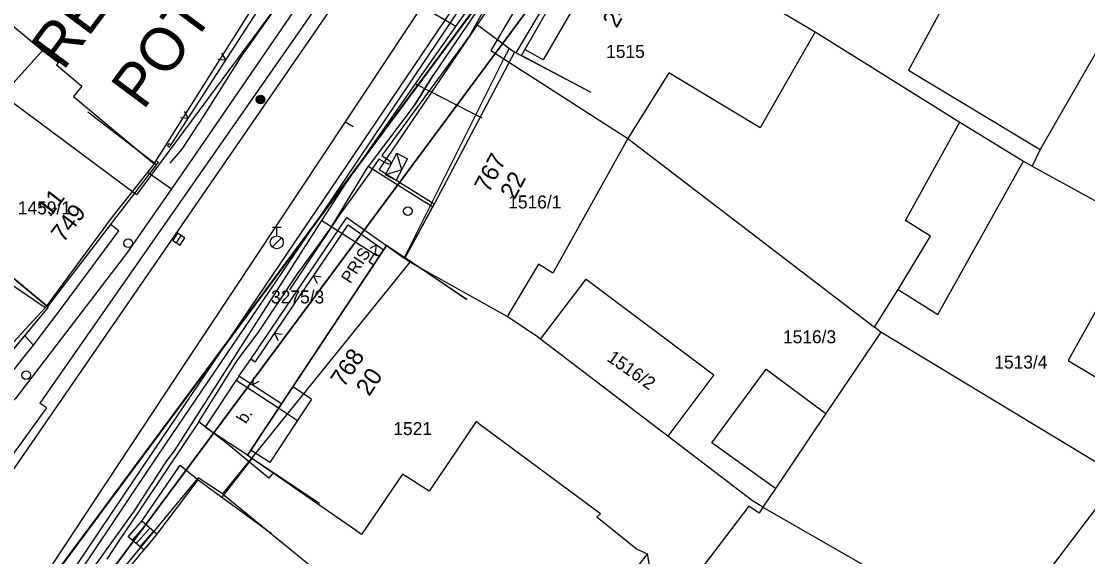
# Model space of a CAD drawing. Extents: x -601580 to 4, y -1204314 to 4.
# Drawn here: x -600312 to -600250.5, y -1203870.6 to -1203839.7 of the extents above; entities that cross this region are included whole.
import ezdxf

# ---------------------------------------------------------------- set-up
doc = ezdxf.new("R2010")
doc.units = 0
for name, color, linetype in [('00-EON NN', 7, 'Continuous'), ('00-INNOGY-NTL', 7, 'Continuous'), ('00-KN-HRANICE PARCEL', 7, 'Continuous'), ('00-KN-PARC. CISLA', 7, 'Continuous'), ('00-KN-VNITRNI KRESBA', 7, 'Continuous'), ('00-POLOHOPIS', 7, 'Continuous'), ('00-RAZÍTKO', 7, 'Continuous'), ('00-SITE KOM. KABEL', 7, 'Continuous'), ('00-VAK-VODA-RAD IGIS', 7, 'Continuous'), ('11-REKONSTRUKCE VODOVOD POPIS', 7, 'Continuous'), ('Vrstva 25', 7, 'Continuous'), ('Vrstva 27', 7, 'Continuous'), ('Vrstva 28', 7, 'Continuous'), ('Vrstva 9', 7, 'Continuous')]:
    doc.layers.add(name, color=color, linetype=linetype)

# ---------------------------------------------------------------- blocks, each defined once
blk = doc.blocks.new('6.14A_88')
at = {"layer": 'Vrstva 28'}
blk.add_circle((0, 0), 0.25, dxfattribs=at)
blk = doc.blocks.new('6.14A_90')
at = {"layer": 'Vrstva 28'}
blk.add_circle((0, 0), 0.25, dxfattribs=at)
blk = doc.blocks.new('6.30_44')
at = {"layer": 'Vrstva 27'}
blk.add_line((-0.25, 0), (0.25, 0), dxfattribs=at)
blk.add_lwpolyline([(-0.25, -0.25), (0.25, -0.25), (0.25, 0.25), (-0.25, 0.25)], close=True, dxfattribs=at)
blk = doc.blocks.new('6.14A_94')
at = {"layer": 'Vrstva 28'}
blk.add_circle((0, 0), 0.25, dxfattribs=at)
blk = doc.blocks.new('6.01A_1052')
at = {"layer": 'Vrstva 25'}
for radius in [0.25, 0.2, 0.15, 0.1, 0.05]:
    blk.add_circle((0, 0), radius, dxfattribs=at)
blk = doc.blocks.new('6.13_78')
at = {"layer": 'Vrstva 28'}
for p, q in [((-0.25, 0.875), (0.25, 0.875)), ((0, 0.375), (0, 0.875)), ((-0.258, -0.272), (0.272, 0.258))]:
    blk.add_line(p, q, dxfattribs=at)
blk.add_circle((0, 0), 0.375, dxfattribs=at)
blk = doc.blocks.new('NN630')
at = {"layer": 'Vrstva 9'}
for points in [[(-3, -700), (-703, 0)], [(-703, -700), (-703, 0), (697, 0), (697, -700)], [(-3, -700), (697, 0)], [(-703, -700), (697, -700)]]:
    blk.add_lwpolyline(points, dxfattribs=at)

msp = doc.modelspace()

# ---------------------------------------------------------------- linework, layer by layer
for points in [[(-600312.703, -1203875.115), (-600310.695, -1203876.605), (-600248.083, -1203792.252), (-600250.091, -1203790.762)], [(-600312.703, -1203875.115), (-600310.695, -1203876.605), (-600248.083, -1203792.252), (-600250.091, -1203790.762)], [(-600312.703, -1203875.115), (-600310.695, -1203876.605), (-600248.083, -1203792.252), (-600250.091, -1203790.762)], [(-600311.213, -1203873.107), (-600251.581, -1203792.77)], [(-600311.213, -1203873.107), (-600251.581, -1203792.77)], [(-600311.213, -1203873.107), (-600251.581, -1203792.77)]]:
    msp.add_lwpolyline(points)
at = {"layer": '00-EON NN'}
for points in [[(-600302.211, -1203810.212), (-600301.35, -1203810.158), (-600300.26, -1203809.69), (-600299, -1203809.18), (-600295.68, -1203811.31), (-600295.91, -1203813.74), (-600299.22, -1203819.65), (-600299.94, -1203821.57), (-600298.78, -1203824.75), (-600294.83, -1203832.08), (-600294.26, -1203833.07), (-600296.42, -1203837.59), (-600299.4, -1203841.82), (-600301.5, -1203845.15), (-600302.77, -1203847.1), (-600303.467, -1203847.911)], [(-600283.734, -1203836.176), (-600286.17, -1203840.55), (-600291.238, -1203847.458), (-600290.75, -1203847.79), (-600290.685, -1203847.95), (-600290.867, -1203847.962), (-600291.397, -1203847.665), (-600291.746, -1203848.17), (-600291.884, -1203848.405), (-600293.721, -1203850.951), (-600296.565, -1203855.206)]]:
    msp.add_lwpolyline(points, dxfattribs=at)
at = {"layer": '00-INNOGY-NTL'}
for p, q in [((-600289.28, -1203843.32), (-600285.46, -1203845.29)), ((-600304.77, -1203848.41), (-600303.37, -1203849.38)), ((-600294.69, -1203851.21), (-600291.52, -1203853.24))]:
    msp.add_line(p, q, dxfattribs=at)
for points in [[(-600286.96, -1203840.01), (-600294.08, -1203835.84), (-600301.99, -1203847.39), (-600303.37, -1203849.38), (-600305.92, -1203853.05), (-600312.38, -1203861.49), (-600319.31, -1203868.9), (-600323.47, -1203873.13), (-600326.97, -1203877.3), (-600332.51, -1203884.94)], [(-600309.72, -1203873.84), (-600305.47, -1203867.91), (-600303.72, -1203865.19), (-600303.17, -1203864.44), (-600294.69, -1203851.21), (-600293.31, -1203849.07), (-600289.28, -1203843.32), (-600286.96, -1203840.01), (-600284.34, -1203836.29)]]:
    msp.add_lwpolyline(points, dxfattribs=at)
at = {"layer": '00-KN-HRANICE PARCEL'}
for p, q in [((-600304.37, -1203847.94), (-600297.5, -1203837.03)), ((-600289.93, -1203853.38), (-600284.19, -1203841.89)), ((-600254.18, -1203847.79), (-600253.67, -1203848.08)), ((-600253.67, -1203848.08), (-600247.28, -1203851.58)), ((-600310.66, -1203856.26), (-600315.41, -1203853.03)), ((-600289.62, -1203853.62), (-600298.75, -1203864.93)), ((-600289.62, -1203853.62), (-600289.93, -1203853.38)), ((-600317.9, -1203864.02), (-600310.66, -1203856.26)), ((-600262.42, -1203857.65), (-600265.58, -1203862.35)), ((-600262.42, -1203857.65), (-600262.77, -1203857.36)), ((-600248.61, -1203866.01), (-600262.42, -1203857.65)), ((-600265.58, -1203862.35), (-600268.5, -1203866.68)), ((-600298.75, -1203864.93), (-600300.43, -1203866.99)), ((-600255.78, -1203875.46), (-600248.61, -1203866.01)), ((-600268.5, -1203866.68), (-600269.22, -1203867.76)), ((-600269.22, -1203867.76), (-600255.78, -1203875.46))]:
    msp.add_line(p, q, dxfattribs=at)
for points in [[(-600320.57, -1203832.25), (-600319.28, -1203833.49), (-600317.47, -1203835.44), (-600314.63, -1203838.22), (-600310.82, -1203841.4), (-600309.9, -1203842.1), (-600310.01, -1203842.23), (-600308.56, -1203843.46), (-600309.03, -1203844.05), (-600304.37, -1203847.94)], [(-600279.86, -1203832.78), (-600284.94, -1203841.4), (-600284.19, -1203841.89)], [(-600279.86, -1203832.78), (-600278.6, -1203833.34), (-600272.16, -1203836.8), (-600266.21, -1203840.33), (-600257.86, -1203845.53), (-600254.18, -1203847.79)], [(-600247.97, -1203837.99), (-600253.21, -1203847.11), (-600253.67, -1203848.08)], [(-600284.19, -1203841.89), (-600277.02, -1203846.48), (-600262.77, -1203857.36)], [(-600262.77, -1203857.36), (-600261.42, -1203855.19), (-600259.13, -1203856.63), (-600254.18, -1203847.79)], [(-600304.37, -1203847.94), (-600306.85, -1203851.07), (-600310.66, -1203856.26)], [(-600247.28, -1203851.58), (-600251.59, -1203859.29), (-600240.31, -1203866.07), (-600242.22, -1203869.32)], [(-600298.75, -1203864.93), (-600298.99, -1203864.76), (-600290.96, -1203852.65), (-600289.93, -1203853.38)], [(-600282.06, -1203858.06), (-600282.24, -1203857.93), (-600284, -1203856.75), (-600289.62, -1203853.62)], [(-600282.06, -1203858.06), (-600279.43, -1203854.6), (-600272.05, -1203860.13), (-600274.71, -1203863.67)], [(-600274.71, -1203863.67), (-600274.95, -1203863.49), (-600282.06, -1203858.06)], [(-600268.5, -1203866.68), (-600272.17, -1203864.05), (-600269.03, -1203859.79), (-600265.58, -1203862.35)], [(-600269.22, -1203867.76), (-600269.82, -1203867.4), (-600274.71, -1203863.67)], [(-600300.43, -1203866.99), (-600301.84, -1203866.07), (-600311.72, -1203878)], [(-600300.43, -1203866.99), (-600295.17, -1203871.27), (-600289.27, -1203875.09), (-600285.06, -1203877.94)], [(-600269.22, -1203867.76), (-600269.44, -1203868.11), (-600270.03, -1203867.7), (-600275.19, -1203874.47), (-600275.88, -1203870.45), (-600282.94, -1203879.26)]]:
    msp.add_lwpolyline(points, dxfattribs=at)
at = {"layer": '00-KN-VNITRNI KRESBA'}
for p, q in [((-600283.47, -1203841.53), (-600278.6, -1203833.34)), ((-600258.59, -1203838.4), (-600260.82, -1203842.53)), ((-600266.21, -1203840.33), (-600269.39, -1203845.87)), ((-600310.82, -1203841.4), (-600312.51, -1203843.28)), ((-600284.19, -1203841.89), (-600283.88, -1203841.31)), ((-600283.88, -1203841.31), (-600283.47, -1203841.53)), ((-600274.66, -1203842.69), (-600277.02, -1203846.48)), ((-600269.39, -1203845.87), (-600274.66, -1203842.69)), ((-600260.82, -1203842.53), (-600253.21, -1203847.11)), ((-600260.98, -1203851.21), (-600257.86, -1203845.53)), ((-600277.02, -1203846.48), (-600281.35, -1203854.26)), ((-600259.55, -1203852.11), (-600260.98, -1203851.21)), ((-600261.42, -1203855.19), (-600259.55, -1203852.11)), ((-600282.19, -1203853.73), (-600284, -1203856.75)), ((-600281.35, -1203854.26), (-600282.19, -1203853.73)), ((-600285.79, -1203862.82), (-600288.5, -1203866.84)), ((-600285.55, -1203863), (-600285.79, -1203862.82)), ((-600278.61, -1203868.14), (-600285.55, -1203863)), ((-600292.81, -1203869.04), (-600298.75, -1203864.93)), ((-600290.03, -1203865.85), (-600292.4, -1203869.33)), ((-600288.5, -1203866.84), (-600290.03, -1203865.85)), ((-600278.82, -1203868.34), (-600278.61, -1203868.14)), ((-600276.55, -1203870.16), (-600278.82, -1203868.34)), ((-600292.4, -1203869.33), (-600292.81, -1203869.04)), ((-600276.55, -1203870.16), (-600275.88, -1203870.45))]:
    msp.add_line(p, q, dxfattribs=at)
at = {"layer": '00-POLOHOPIS'}
for p, q in [((-600292.434, -1203846.854), (-600277.773, -1203825.148)), ((-600285.704, -1203839.927), (-600279.491, -1203830.538)), ((-600293.822, -1203837.167), (-600310.976, -1203861.752)), ((-600318.438, -1203874.2), (-600293.21, -1203837.594)), ((-600280.074, -1203838.762), (-600281.921, -1203841.941)), ((-600291.374, -1203848.295), (-600285.704, -1203839.927)), ((-600285.704, -1203839.927), (-600283.568, -1203841.492)), ((-600281.921, -1203841.941), (-600282.962, -1203841.345)), ((-600304.344, -1203864.405), (-600292.434, -1203846.854)), ((-600303.519, -1203846.766), (-600303.611, -1203846.909)), ((-600303.611, -1203846.909), (-600303.485, -1203846.99)), ((-600303.519, -1203846.766), (-600303.393, -1203846.847)), ((-600304.263, -1203847.757), (-600304.366, -1203847.892)), ((-600304.263, -1203847.757), (-600304.144, -1203847.848)), ((-600304.144, -1203847.848), (-600304.247, -1203847.983)), ((-600288.21, -1203850.274), (-600291.374, -1203848.295)), ((-600289.644, -1203852.932), (-600288.281, -1203850.406)), ((-600298.797, -1203859.226), (-600293.241, -1203851.048)), ((-600293.241, -1203851.048), (-600290.954, -1203852.655)), ((-600291.967, -1203853.602), (-600291.635, -1203853.102)), ((-600291.635, -1203853.102), (-600291.368, -1203853.279)), ((-600291.967, -1203853.602), (-600291.7, -1203853.779)), ((-600310.495, -1203856.212), (-600313.446, -1203859.756)), ((-600299.48, -1203860.194), (-600298.797, -1203859.226)), ((-600298.549, -1203859.395), (-600298.797, -1203859.226)), ((-600301.423, -1203863.165), (-600299.644, -1203860.445)), ((-600299.48, -1203860.194), (-600299.644, -1203860.445)), ((-600297.19, -1203862.05), (-600299.644, -1203860.445)), ((-600295.281, -1203861.523), (-600296.365, -1203860.805)), ((-600310.591, -1203862.021), (-600310.976, -1203861.752)), ((-600295.281, -1203861.523), (-600297.703, -1203865.177)), ((-600310.591, -1203862.021), (-600319.085, -1203873.73)), ((-600296.106, -1203862.768), (-600297.19, -1203862.05)), ((-600298.987, -1203864.761), (-600301.423, -1203863.165)), ((-600312.785, -1203876.933), (-600304.344, -1203864.405)), ((-600298.724, -1203864.922), (-600300.459, -1203867.173)), ((-600297.703, -1203865.177), (-600298.787, -1203864.459)), ((-600305.082, -1203868.573), (-600302.881, -1203865.34)), ((-600302.881, -1203865.34), (-600301.825, -1203866.173)), ((-600305.875, -1203869.473), (-600305.082, -1203868.573)), ((-600304.215, -1203869.317), (-600305.082, -1203868.573)), ((-600305.644, -1203869.665), (-600304.856, -1203868.771)), ((-600305.413, -1203869.856), (-600304.631, -1203868.969)), ((-600305.182, -1203870.048), (-600304.406, -1203869.167)), ((-600304.215, -1203869.317), (-600304.83, -1203870.06)), ((-600304.967, -1203870.226), (-600305.875, -1203869.473))]:
    msp.add_line(p, q, dxfattribs=at)
for points in [[(-600279.148, -1203843.829), (-600283.163, -1203841.696), (-600278.436, -1203833.446), (-600275.222, -1203835.278)], [(-600303.485, -1203846.99), (-600297.185, -1203837.2)], [(-600300.683, -1203841.896), (-600300.238, -1203841.944), (-600300.466, -1203841.56)], [(-600279.148, -1203843.829), (-600283.568, -1203841.492), (-600288.21, -1203850.274), (-600289.872, -1203853.355), (-600286.312, -1203855.78)], [(-600308.215, -1203844.941), (-600304.247, -1203847.983), (-600310.532, -1203856.18), (-600314.337, -1203853.013)], [(-600302.847, -1203845.26), (-600302.403, -1203845.308), (-600302.631, -1203844.923)], [(-600296.301, -1203856.086), (-600294.053, -1203852.777), (-600293.164, -1203851.469)], [(-600293.164, -1203851.469), (-600291.126, -1203852.9)], [(-600286.312, -1203855.78), (-600290.954, -1203852.655), (-600296.365, -1203860.805), (-600298.987, -1203864.761), (-600294.819, -1203867.523)], [(-600291.594, -1203853.061), (-600291.528, -1203852.618), (-600291.921, -1203852.831)], [(-600314.337, -1203853.013), (-600310.495, -1203856.212), (-600313.446, -1203859.756), (-600317.583, -1203864.365), (-600321.298, -1203861.018)], [(-600294.734, -1203854.491), (-600295.177, -1203854.432), (-600294.959, -1203854.822)], [(-600298.549, -1203859.394), (-600296.301, -1203856.086)], [(-600296.982, -1203857.8), (-600297.425, -1203857.74), (-600297.206, -1203858.13)], [(-600297.026, -1203861.798), (-600299.48, -1203860.194)], [(-600298.648, -1203860.26), (-600298.7, -1203860.704), (-600298.313, -1203860.479)], [(-600308.026, -1203881.169), (-600310.442, -1203879.054), (-600311.559, -1203878.04), (-600308.953, -1203875.032), (-600304.224, -1203869.329), (-600301.825, -1203866.173), (-600297.617, -1203869.254)]]:
    msp.add_lwpolyline(points, dxfattribs=at)
at = {"layer": '00-RAZÍTKO'}
for points in [[(-600492.548, -1203872.448), (-600304.712, -1203619.391), (-600185.471, -1203707.9), (-600373.307, -1203960.957)], [(-600489.051, -1203871.931), (-600304.195, -1203622.889), (-600188.969, -1203708.417), (-600373.825, -1203957.46)]]:
    msp.add_lwpolyline(points, close=True, dxfattribs=at)
at = {"layer": '00-SITE KOM. KABEL'}
for points in [[(-600319.96, -1203891.12), (-600321.17, -1203890.19), (-600304.06, -1203864.65), (-600294.17, -1203850.07), (-600282.45, -1203832.63), (-600279.97, -1203828.88), (-600279.74, -1203826.75), (-600273.69, -1203817.55), (-600271.37, -1203815.37), (-600264.47, -1203805.03), (-600246.59, -1203780.19), (-600235.23, -1203765.23)], [(-600283.33, -1203835.43), (-600283.8, -1203836.17), (-600286.01, -1203839.51), (-600288.27, -1203842.83), (-600289.3, -1203844.49), (-600292.02, -1203848.09)], [(-600289.3, -1203844.49), (-600288.27, -1203842.83)], [(-600301.79, -1203862.84), (-600299.58, -1203859.3), (-600298.38, -1203857.71), (-600296.14, -1203854.35), (-600294.78, -1203852.5), (-600294.18, -1203851.64), (-600292.02, -1203848.09)], [(-600294.18, -1203851.64), (-600292.02, -1203848.09)], [(-600288.29, -1203850.43), (-600288.84, -1203850.09), (-600292.02, -1203848.09)], [(-600311.34, -1203858.41), (-600309.66, -1203856.2), (-600306.41, -1203851.81), (-600306.9, -1203851.44)], [(-600294.78, -1203852.5), (-600294.18, -1203851.64)], [(-600298.38, -1203857.71), (-600296.14, -1203854.35)], [(-600311.87, -1203857.86), (-600311.34, -1203858.41)], [(-600319.59, -1203867.6), (-600318.11, -1203866.27), (-600313.88, -1203861.36), (-600312.73, -1203860.16), (-600311.97, -1203859.2), (-600311.34, -1203858.41)], [(-600301.79, -1203862.84), (-600299.58, -1203859.3)], [(-600301.79, -1203862.84), (-600303.65, -1203865.58), (-600305.28, -1203868.02), (-600306.41, -1203869.7), (-600307.1, -1203870.76)], [(-600301.79, -1203862.84), (-600303.65, -1203865.58)], [(-600297.49, -1203865.76), (-600297.75, -1203866.08), (-600300.19, -1203864.06), (-600301.79, -1203862.84)], [(-600305.28, -1203868.02), (-600306.41, -1203869.7)]]:
    msp.add_lwpolyline(points, dxfattribs=at)
at = {"layer": '00-VAK-VODA-RAD IGIS'}
for points in [[(-600276.695, -1203819.684), (-600279.39, -1203823.44), (-600280.72, -1203826.32), (-600281.68, -1203827.91), (-600293.34, -1203845.51), (-600302.48, -1203859.3), (-600311.62, -1203873.1), (-600313.81, -1203875.29), (-600320.66, -1203886.26), (-600323.71, -1203891.56), (-600327.34, -1203898.14), (-600331.383, -1203905.452), (-600338.1, -1203917.89), (-600346.75, -1203940.93), (-600353.201, -1203956.994), (-600355.466, -1203962.632), (-600360.94, -1203972.29), (-600370.25, -1203987.62), (-600375.59, -1203995.85), (-600378.929, -1203999.479), (-600379.29, -1204000.12)], [(-600293.34, -1203845.51), (-600292.883, -1203845.785)]]:
    msp.add_lwpolyline(points, dxfattribs=at)
at = {"layer": '11-REKONSTRUKCE VODOVOD POPIS'}
msp.add_lwpolyline([(-600316.018, -1203841.848), (-600272.765, -1203783.577), (-600262.149, -1203791.457), (-600305.402, -1203849.728)], close=True, dxfattribs=at)
msp.add_lwpolyline([(-600316.018, -1203841.848), (-600272.765, -1203783.577), (-600262.149, -1203791.457), (-600305.402, -1203849.728)], close=True, dxfattribs=at)

# ---------------------------------------------------------------- block references
at = {"layer": '00-EON NN', "xscale": 0.001, "yscale": 0.001, "rotation": 62.139911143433}
msp.add_blockref('NN630', (-600290.685, -1203847.95), dxfattribs=at)
at = {"layer": '00-POLOHOPIS', "rotation": -90.00000000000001}
for name, p in [('6.01A_1052', (-600298.227, -1203844.227)), ('6.14A_94', (-600289.733, -1203850.676)), ('6.14A_88', (-600305.88, -1203852.529)), ('6.14A_90', (-600311.76, -1203860.14))]:
    msp.add_blockref(name, p, dxfattribs=at)
at = {"layer": '00-POLOHOPIS', "xscale": 1.00000014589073, "yscale": 1.0000001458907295, "rotation": 56.403762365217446}
msp.add_blockref('6.30_44', (-600302.951, -1203852.292), dxfattribs=at)
at = {"layer": '00-POLOHOPIS'}
msp.add_blockref('6.13_78', (-600297.294, -1203852.473), dxfattribs=at)

# ---------------------------------------------------------------- texts
at = {"layer": '00-KN-PARC. CISLA'}
for s, p in [('1515', (-600278.275, -1203841.83)), ('1459/1', (-600312.249, -1203850.86)), ('1516/1', (-600283.929, -1203850.52)), ('3275/3', (-600297.623, -1203856)), ('1516/3', (-600268.063, -1203858.3)), ('1513/4', (-600255.861, -1203859.76)), ('1521', (-600290.564, -1203863.6))]:
    msp.add_text(s, height=0.75, dxfattribs=at).set_placement(p)
msp.add_text('1516/2', height=0.75, rotation=325, dxfattribs=at).set_placement((-600278.283, -1203859.275))
at = {"layer": '00-POLOHOPIS'}
for s, height, rotation, p in [('24', 1, 60.17524, (-600277.673, -1203840.157)), ('767', 1, 62.13991, (-600285.059, -1203849.663)), ('22', 1, 62.13991, (-600283.572, -1203850.059)), ('11', 1, 52.52127, (-600310.39, -1203851.064)), ('749', 1, 52.52127, (-600309.624, -1203852.53)), ('PRIS', 0.7, 56.41584, (-600293.051, -1203854.9)), ('768', 1, 56.41877, (-600293.427, -1203860.899)), ('20', 1, 56.41877, (-600291.964, -1203861.408)), ('b.', 0.7, 57.9182, (-600299.079, -1203862.991))]:
    msp.add_text(s, height=height, rotation=rotation, dxfattribs=at).set_placement(p)
at = {"layer": '11-REKONSTRUKCE VODOVOD POPIS'}
for s, p in [('REKONSTRUKCE VODOVODU 202.72 m', (-600309.63, -1203842.616)), (' POTRUBÍ PE DN100 ', (-600305.553, -1203845.643))]:
    msp.add_text(s, height=2.5, rotation=53.41468, dxfattribs=at).set_placement(p)

doc.saveas('drawing.dxf')
